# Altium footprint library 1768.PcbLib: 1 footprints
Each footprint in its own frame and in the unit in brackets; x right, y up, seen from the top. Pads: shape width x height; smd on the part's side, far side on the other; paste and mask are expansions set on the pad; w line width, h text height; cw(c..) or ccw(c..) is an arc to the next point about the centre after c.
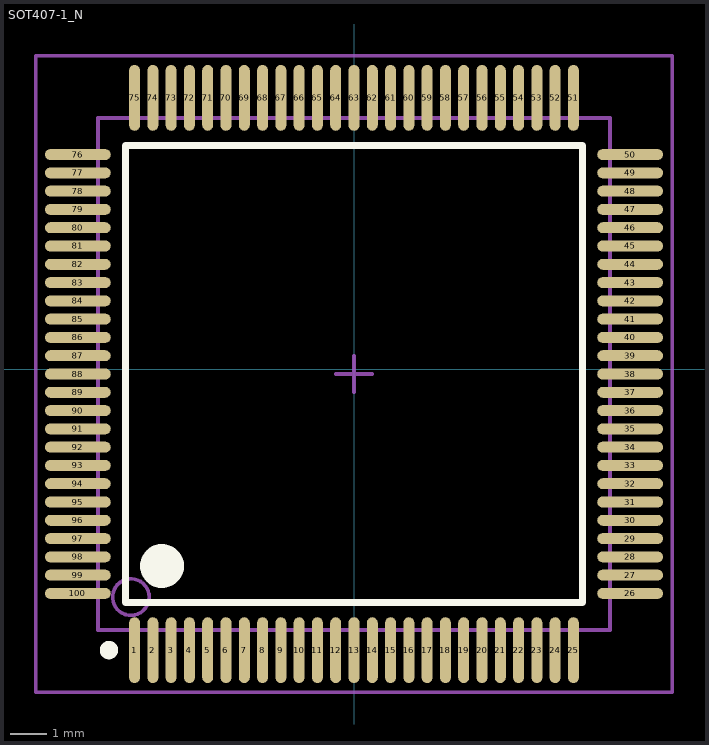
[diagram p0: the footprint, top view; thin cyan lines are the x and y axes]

## SOT407-1_N [mm]
height 3
pads (100):
  oval 0.3x1.8 smd: 1(-6,-7.677) 2(-5.5,-7.677) 3(-5,-7.677) 4(-4.5,-7.677) 5(-4,-7.677) 6(-3.5,-7.677) 7(-3,-7.677) 8(-2.5,-7.677) 9(-2,-7.677) 10(-1.5,-7.677) 11(-1,-7.677) 12(-0.5,-7.677) 13(0,-7.677) 14(0.5,-7.677) 15(1,-7.677) 16(1.5,-7.677) 17(2,-7.677) 18(2.5,-7.677) 19(3,-7.677) 20(3.5,-7.677) 21(4,-7.677) 22(4.5,-7.677) 23(5,-7.677) 24(5.5,-7.677) 25(6,-7.677) 51(6,7.423) 52(5.5,7.423) 53(5,7.423) 54(4.5,7.423) 55(4,7.423) 56(3.5,7.423) 57(3,7.423) 58(2.5,7.423) 59(2,7.423) 60(1.5,7.423) 61(1,7.423) 62(0.5,7.423) 63(0,7.423) 64(-0.5,7.423) 65(-1,7.423) 66(-1.5,7.423) 67(-2,7.423) 68(-2.5,7.423) 69(-3,7.423) 70(-3.5,7.423) 71(-4,7.423) 72(-4.5,7.423) 73(-5,7.423) 74(-5.5,7.423) 75(-6,7.423)
  oval 1.8x0.3 smd: 26(7.55,-6.127) 27(7.55,-5.627) 28(7.55,-5.127) 29(7.55,-4.627) 30(7.55,-4.127) 31(7.55,-3.627) 32(7.55,-3.127) 33(7.55,-2.627) 34(7.55,-2.127) 35(7.55,-1.627) 36(7.55,-1.127) 37(7.55,-0.627) 38(7.55,-0.127) 39(7.55,0.373) 40(7.55,0.873) 41(7.55,1.373) 42(7.55,1.873) 43(7.55,2.373) 44(7.55,2.873) 45(7.55,3.373) 46(7.55,3.873) 47(7.55,4.373) 48(7.55,4.873) 49(7.55,5.373) 50(7.55,5.873) 76(-7.55,5.873) 77(-7.55,5.373) 78(-7.55,4.873) 79(-7.55,4.373) 80(-7.55,3.873) 81(-7.55,3.373) 82(-7.55,2.873) 83(-7.55,2.373) 84(-7.55,1.873) 85(-7.55,1.373) 86(-7.55,0.873) 87(-7.55,0.373) 88(-7.55,-0.127) 89(-7.55,-0.627) 90(-7.55,-1.127) 91(-7.55,-1.627) 92(-7.55,-2.127) 93(-7.55,-2.627) 94(-7.55,-3.127) 95(-7.55,-3.627) 96(-7.55,-4.127) 97(-7.55,-4.627) 98(-7.55,-5.127) 99(-7.55,-5.627) 100(-7.55,-6.127)
Top Overlay:
  circle w0.6: c-5.25,-5.377 r0.3
  circle w0.25: c-6.7,-7.677 r0.125
  lines w0.2: -6.25,-6.377 -6.25,6.123 6.25,6.123 6.25,-6.377 -6.25,-6.377
Mechanical 13:
  circle w0.1: c-6.1,-6.227 r0.5
  lines w0.1: -7,-7.127 -7,6.873 7,6.873 7,-7.127 -7,-7.127
Mechanical 15:
  lines w0.1: -0.5,-0.127 0.5,-0.127 ; 0,-0.627 0,0.373 ; -8.7,-8.827 -8.7,8.573 8.7,8.573 8.7,-8.827 -8.7,-8.827
3D body: height 1.6, standoff 0, extent -7,-7.127 7,6.873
